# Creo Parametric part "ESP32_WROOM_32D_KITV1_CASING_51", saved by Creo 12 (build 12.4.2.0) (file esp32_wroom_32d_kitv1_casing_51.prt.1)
Units: Custom; MM, KILOGRAM, SECS

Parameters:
  PTC_WM_ITERATION = "0"
  PTC_WM_VERSION = "-.0"
  PTC_WM_LIFECYCLE_STATE = "In Work"
  PTC_WM_LIFECYCLE = "MO_CADDocument"
  PTC_WM_CREATED_BY = "Maximilian Roepper (Z0017RMS: MO)"
  PTC_WM_CREATED_ON = "18-Sep-26 11:36:42 AM"
  PTC_WM_MODIFIED_BY = "Maximilian Roepper (Z0017RMS: MO)"
  PTC_WM_MODIFIED_ON = "18-Sep-26 11:36:46 AM"
  PDMLINKNUMBER = "PDM000071454981"
  PTC_WM_NAME = "esp32_wroom_32d_kitv1_casing_51.prt"
  PTC_WM_NUMBER = "PDM000071454981"

Other parameters: WEIGHT, WEIGHT_FACTOR, WEIGHT_ADD, _MASS_TEMP, _DIFF_TEMP, MC_ERRORS, SUPPLIER

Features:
  1. coordinate system
  2. datum plane "PRT_YZ"
  3. datum plane "PRT_XY"
  4. datum plane "PRT_XZ"
  5. coordinate system
  6. datum axis
  7. datum axis
  8. datum axis
  9. coordinate system
  10. imported feature
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
Other named items: PRT, SIEMENS_MO, DRW_VIEW_ORG, PRT_X, PRT_Y, PRT_Z, CS0, ROUGH_GROB

Layers: 00_STD_CSYS-KSYS, 01_STD_PLANES-EBENEN, 02_STD_AXES-ACHSEN, 03_STD_CSYS-KSYS, 24_IMPORT_FEAT-IMPORT_KE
